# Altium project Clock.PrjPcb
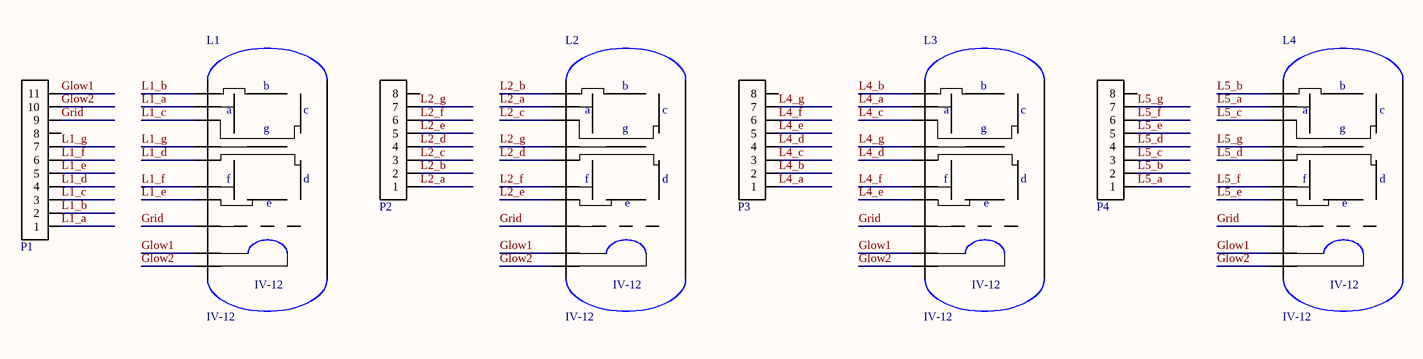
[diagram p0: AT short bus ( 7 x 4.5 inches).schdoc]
1 sheet, 8 parts. Net scope: global (net labels, ports and power ports of the same name join across sheets).
Board file: AT short bus ( 7 x 4.5 inches).PCBDOC

## Sheet AT short bus ( 7 x 4.5 inches).schdoc: AT short bus ( 7 x 4.5 inches)
size A3; Organization: Organization; Address1: Address1; Address2: Address2; Address3: Address3; Address4: Address4; DocumentNumber: 1; Revision: 0; SheetNumber: 2; SheetTotal: 2

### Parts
L1  IV-12  [IV-12]
L2  IV-12  [IV-12]
L3  IV-12  [IV-12]
L4  IV-12  [IV-12]
P1  Header 11  [HDR1X11]  (value not drawn)
P2  Header 8  [HDR1X8]  (value not drawn)
P3  Header 8  [HDR1X8]  (value not drawn)
P4  Header 8  [HDR1X8]  (value not drawn)

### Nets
Glow1: L1.3 L2.3 L3.3 L4.3 P1.11
Glow2: L1.2 L2.2 L3.2 L4.2 P1.10
Grid: L1.4 L2.4 L3.4 L4.4 P1.9
L1_a: L1.10 P1.1
L1_b: L1.8 P1.2
L1_c: L1.7 P1.3
L1_d: L1.6 P1.4
L1_e: L1.5 P1.5
L1_f: L1.1 P1.6
L1_g: L1.9 P1.7
L2_a: L2.10 P2.1
L2_b: L2.8 P2.2
L2_c: L2.7 P2.3
L2_d: L2.6 P2.4
L2_e: L2.5 P2.5
L2_f: L2.1 P2.6
L2_g: L2.9 P2.7
L4_a: L3.10 P3.1
L4_b: L3.8 P3.2
L4_c: L3.7 P3.3
L4_d: L3.6 P3.4
L4_e: L3.5 P3.5
L4_f: L3.1 P3.6
L4_g: L3.9 P3.7
L5_a: L4.10 P4.1
L5_b: L4.8 P4.2
L5_c: L4.7 P4.3
L5_d: L4.6 P4.4
L5_e: L4.5 P4.5
L5_f: L4.1 P4.6
L5_g: L4.9 P4.7

Not connected (* = marked no-connect by the designer): P1 8; P2 8; P3 8; P4 8

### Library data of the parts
L1-L4 = Lamp1_IV-12
P1 = Header 11: Header, 11-Pin
P2-P4 = Header 8: Header, 8-Pin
